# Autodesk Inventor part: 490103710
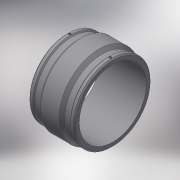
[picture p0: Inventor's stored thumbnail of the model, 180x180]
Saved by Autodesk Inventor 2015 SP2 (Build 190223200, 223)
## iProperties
Created: 2017-06
Part Number: 490103710
Material: Generic
Description: PLASSON COUPLER 710
Document SubType Name: Modeling
Designer: KIM
Mass: 16398.8 g
Surface Area: 10528.4 cm^2
Volume: 16398.8 cm^3
Density: 1 g/cm^3
Appearance: Default
Author: KIM
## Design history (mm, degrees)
derived "490103.ipt"
feature "Solid1::490103.ipt"
tag "TaggingFeature1"
body "Solid1"
other parameters: "d13" = 472, "d15" = 236, "d16" = 236, "d23" = 853, "d24" = 776, "d25" = 135 deg, "d26" = 188.8, "d27" = 135 deg, "d35" = 15, "d39" = 0, "d40" = 4, "d41" = 14, "d42" = 0, "d43" = 135 deg, "d44" = 51.92, "d46" = 6, "d47" = 0, "L_" = 472, "L_1" = 236, "D_" = 853, "d_2" = 12
